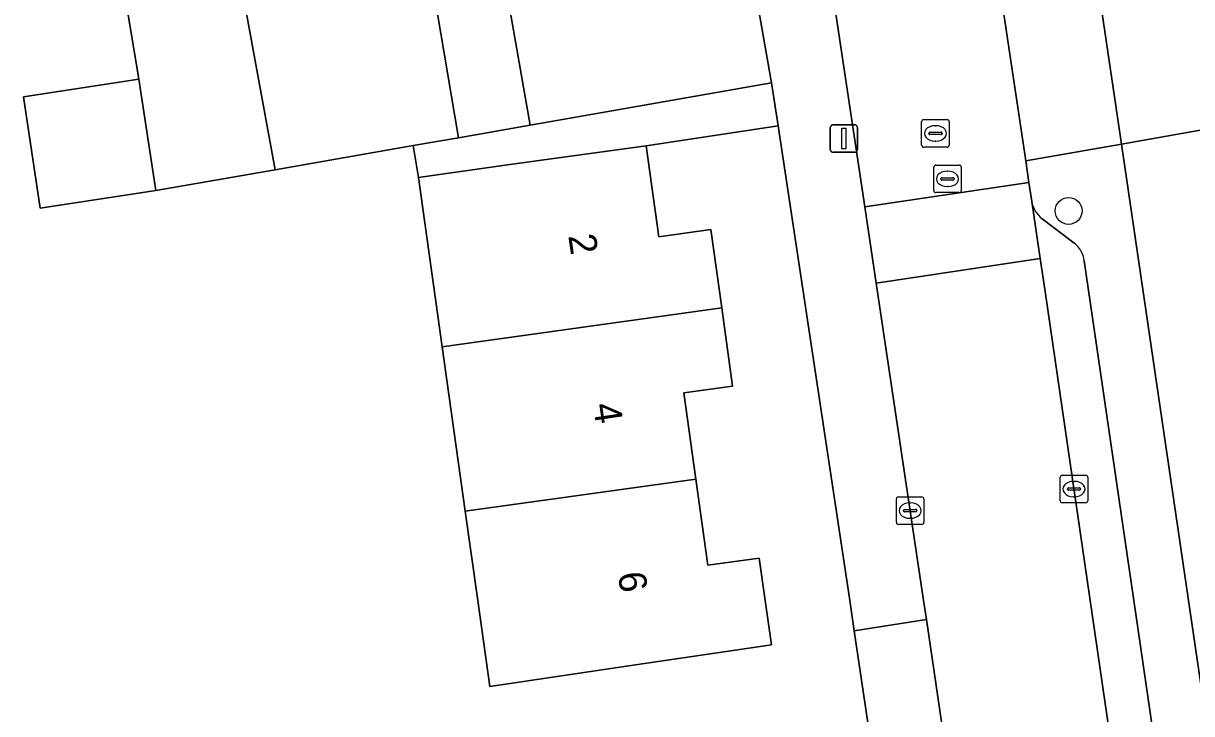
# Model space of a CAD drawing. Extents: x 159053 to 160042, y 380449 to 381423.
# Drawn here: x 159449.7 to 159492.17, y 381245.81 to 381270.89 of the extents above; entities that cross this region are included whole.
import ezdxf

# ---------------------------------------------------------------- set-up
doc = ezdxf.new("R2010")
doc.units = 0
for name, color, linetype in [('IMGEO_Boom', 7, 'Continuous'), ('IMGEO_Erf', 7, 'Continuous'), ('IMGEO_Inrit_open', 7, 'Continuous'), ('IMGEO_Kolk', 7, 'Continuous'), ('IMGEO_Lichtmast', 7, 'Continuous'), ('IMGEO_Pand', 7, 'Continuous'), ('IMGEO_Pand_nummerreeks', 7, 'Continuous'), ('IMGEO_Parkeervlak_open', 7, 'Continuous'), ('IMGEO_Rijbaan_lokaal_open', 7, 'Continuous'), ('IMGEO_Rioolput', 7, 'Continuous'), ('IMGEO_Voetpad_open', 7, 'Continuous')]:
    doc.layers.add(name, color=color, linetype=linetype)

msp = doc.modelspace()

# ---------------------------------------------------------------- linework, layer by layer
at = {"layer": 'IMGEO_Boom'}
msp.add_circle((159487.7, 381264.074), 0.489, dxfattribs=at)
at = {"layer": 'IMGEO_Erf'}
for points in [[(159464.93, 381259.134), (159464.069, 381265.292), (159463.868, 381266.446), (159458.856, 381265.571), (159454.511, 381264.813), (159450.316, 381264.174), (159449.701, 381268.222), (159453.895, 381268.86), (159452.908, 381274.851)], [(159464.746, 381271.31), (159465.519, 381266.734), (159468.12, 381267.188), (159467.326, 381271.758)], [(159480.617, 381244.005), (159479.909, 381248.818), (159479.731, 381250), (159477.138, 381267.167), (159472.343, 381266.443), (159472.803, 381263.137), (159474.692, 381263.4), (159475.088, 381260.552), (159475.485, 381257.704), (159473.711, 381257.458), (159474.146, 381254.33), (159474.581, 381251.2), (159476.448, 381251.46), (159476.655, 381250), (159476.896, 381248.305), (159471.95, 381247.577), (159466.654, 381246.797), (159466.206, 381250), (159465.764, 381253.165), (159464.93, 381259.134)], [(159493.853, 381267.251), (159489.62, 381266.493), (159492.045, 381250), (159496.747, 381218.013)]]:
    msp.add_lwpolyline(points, dxfattribs=at)
at = {"layer": 'IMGEO_Inrit_open'}
msp.add_lwpolyline([(159488.87, 381271.571), (159488.814, 381271.948), (159485.313, 381271.467), (159486.141, 381265.894), (159489.62, 381266.493)], close=True, dxfattribs=at)
at = {"layer": 'IMGEO_Kolk'}
for p, q in [((159487.395, 381253.542), (159487.395, 381254.394)), ((159487.47, 381254.468), (159488.322, 381254.468)), ((159487.883, 381254.248), (159487.908, 381254.248)), ((159488.396, 381254.394), (159488.396, 381253.542)), ((159481.513, 381253.685), (159482.365, 381253.685)), ((159487.654, 381253.962), (159487.654, 381253.974)), ((159488.092, 381253.925), (159487.694, 381253.925)), ((159487.697, 381254.011), (159488.095, 381254.011)), ((159487.906, 381253.688), (159487.881, 381253.688)), ((159488.138, 381253.974), (159488.138, 381253.962)), ((159481.438, 381252.759), (159481.438, 381253.611)), ((159481.926, 381253.465), (159481.951, 381253.465)), ((159482.439, 381253.611), (159482.439, 381252.759)), ((159488.322, 381253.468), (159487.47, 381253.468)), ((159481.697, 381253.179), (159481.697, 381253.191)), ((159482.135, 381253.142), (159481.737, 381253.142)), ((159481.74, 381253.228), (159482.138, 381253.228)), ((159481.949, 381252.905), (159481.924, 381252.905)), ((159482.181, 381253.191), (159482.181, 381253.179)), ((159482.365, 381252.685), (159481.513, 381252.685))]:
    msp.add_line(p, q, dxfattribs=at)
for points in [[(159487.395, 381253.542), (159487.395, 381254.394)], [(159487.47, 381254.468), (159488.322, 381254.468)], [(159488.396, 381254.394), (159488.396, 381253.542)], [(159481.513, 381253.685), (159482.365, 381253.685)], [(159481.438, 381252.759), (159481.438, 381253.611)], [(159482.439, 381253.611), (159482.439, 381252.759)], [(159488.322, 381253.468), (159487.47, 381253.468)], [(159482.365, 381252.685), (159481.513, 381252.685)]]:
    msp.add_lwpolyline(points, dxfattribs=at)
for centre, radius, start, end in [((159487.472, 381254.392), 0.0765, 91.552, 178.448), ((159487.472, 381254.392), 0.0765, 91.552, 178.448), ((159488.32, 381254.392), 0.0765, 1.552, 88.448), ((159488.32, 381254.392), 0.0765, 1.552, 88.448), ((159481.515, 381253.609), 0.0765, 91.552, 178.448), ((159481.515, 381253.609), 0.0765, 91.552, 178.448), ((159482.363, 381253.609), 0.0765, 1.552, 88.448), ((159482.363, 381253.609), 0.0765, 1.552, 88.448), ((159487.694, 381253.971), 0.0403, 85.8775, 175.7526), ((159487.691, 381253.961), 0.0366, 178.938, 274.7102), ((159488.095, 381253.968), 0.043, 264.8664, 352.4533), ((159488.099, 381253.973), 0.0386, 1.7309, 96.639), ((159487.472, 381253.544), 0.0765, 181.552, 268.448), ((159487.472, 381253.544), 0.0765, 181.552, 268.448), ((159488.32, 381253.544), 0.0765, 271.552, 358.448), ((159488.32, 381253.544), 0.0765, 271.552, 358.448), ((159481.737, 381253.188), 0.0403, 85.8775, 175.7526), ((159481.734, 381253.178), 0.0366, 178.938, 274.7102), ((159482.138, 381253.185), 0.043, 264.8664, 352.4533), ((159482.142, 381253.19), 0.0386, 1.7309, 96.639), ((159481.515, 381252.761), 0.0765, 181.552, 268.448), ((159481.515, 381252.761), 0.0765, 181.552, 268.448), ((159482.363, 381252.761), 0.0765, 271.552, 358.448), ((159482.363, 381252.761), 0.0765, 271.552, 358.448)]:
    msp.add_arc(centre, radius, start, end, dxfattribs=at)
for centre, major_axis, ratio, start_param, end_param in [((159487.882, 381253.968), (-0.387, 0.002), 0.722429, 4.712389, 7.853982), ((159487.907, 381253.968), (-0.39, 0.002), 0.717154, 1.570796, 4.712389), ((159481.925, 381253.185), (-0.387, 0.002), 0.722429, 4.712389, 7.853982), ((159481.95, 381253.185), (-0.39, 0.002), 0.717154, 1.570796, 4.712389)]:
    msp.add_ellipse(centre, major_axis=major_axis, ratio=ratio, start_param=start_param, end_param=end_param, dxfattribs=at)
at = {"layer": 'IMGEO_Lichtmast'}
for p, q in [((159479.034, 381266.304), (159479.034, 381267.104)), ((159479.034, 381267.104), (159479.034, 381266.304)), ((159479.134, 381267.204), (159479.924, 381267.204)), ((159479.924, 381267.204), (159479.134, 381267.204)), ((159480.024, 381267.104), (159480.024, 381266.304)), ((159480.024, 381266.304), (159480.024, 381267.104)), ((159479.924, 381266.204), (159479.134, 381266.204)), ((159479.134, 381266.204), (159479.924, 381266.204))]:
    msp.add_line(p, q, dxfattribs=at)
msp.add_lwpolyline([(159479.454, 381267.079), (159479.604, 381267.079), (159479.604, 381266.329), (159479.454, 381266.329), (159479.454, 381267.079)], dxfattribs=at)
for centre, start, end in [((159479.134, 381267.104), 90, 180), ((159479.134, 381267.104), 90, 180), ((159479.924, 381267.104), 0, 90), ((159479.924, 381267.104), 360, 90), ((159479.134, 381266.304), 180, 270), ((159479.134, 381266.304), 180, 270), ((159479.924, 381266.304), 270, 0), ((159479.924, 381266.304), 270, 0)]:
    msp.add_arc(centre, 0.1, start, end, dxfattribs=at)
at = {"layer": 'IMGEO_Pand'}
for points in [[(159458.856, 381265.571), (159457.03, 381275.544), (159452.908, 381274.851), (159453.895, 381268.86), (159454.511, 381264.813)], [(159464.012, 381275.652), (159460.304, 381275.025), (159457.03, 381275.544), (159458.856, 381265.571), (159463.868, 381266.446), (159465.519, 381266.734), (159464.746, 381271.31)], [(159476.317, 381272.048), (159473.321, 381271.528), (159473.107, 381272.762), (159467.326, 381271.758), (159468.12, 381267.188), (159476.903, 381268.722)], [(159454.511, 381264.813), (159453.895, 381268.86), (159449.701, 381268.222), (159450.316, 381264.174)], [(159464.93, 381259.134), (159475.088, 381260.552), (159474.692, 381263.4), (159472.803, 381263.137), (159472.343, 381266.443), (159467.391, 381265.754), (159464.069, 381265.292)], [(159464.93, 381259.134), (159465.764, 381253.165), (159474.146, 381254.33), (159473.711, 381257.458), (159475.485, 381257.704), (159475.088, 381260.552)], [(159465.764, 381253.165), (159466.206, 381250), (159466.654, 381246.797), (159471.95, 381247.577), (159476.896, 381248.305), (159476.655, 381250), (159476.448, 381251.46), (159474.581, 381251.2), (159474.146, 381254.33)]]:
    msp.add_lwpolyline(points, close=True, dxfattribs=at)
at = {"layer": 'IMGEO_Parkeervlak_open'}
for points in [[(159486.361, 381264.417), (159486.669, 381262.342), (159486.847, 381261.146), (159488.473, 381250), (159492.258, 381224.048), (159493.062, 381218.662)], [(159487.888, 381262.912), (159486.742, 381263.785)], [(159494.208, 381221.574), (159490.06, 381250), (159488.271, 381262.261)]]:
    msp.add_lwpolyline(points, dxfattribs=at)
for centre, radius, start, end in [((159487.317, 381264.563), 0.967, 188.6582, 233.509), ((159487.278, 381262.115), 1.004, 8.3707, 52.5681)]:
    msp.add_arc(centre, radius, start, end, dxfattribs=at)
at = {"layer": 'IMGEO_Rijbaan_lokaal_open'}
for points in [[(159485.313, 381271.467), (159484.524, 381276.78), (159484.001, 381280.293), (159483.708, 381282.207), (159481.469, 381296.819), (159481.293, 381297.861), (159481.275, 381298.091), (159475.346, 381297.113), (159475.58, 381295.695), (159475.809, 381294.223), (159476.504, 381289.652), (159478.964, 381273.094), (159479.515, 381269.384), (159480.289, 381264.217), (159486.258, 381265.111), (159486.141, 381265.894)], [(159486.361, 381264.417), (159486.258, 381265.111), (159480.289, 381264.217), (159480.703, 381261.448), (159486.669, 381262.342)], [(159488.473, 381250), (159486.847, 381261.146), (159486.669, 381262.342), (159480.703, 381261.448), (159482.417, 381250), (159482.532, 381249.232), (159483.241, 381244.433), (159487.143, 381218.031), (159487.557, 381215.23), (159487.948, 381212.582), (159493.859, 381213.326), (159493.18, 381217.872), (159493.062, 381218.662), (159492.258, 381224.048)]]:
    msp.add_lwpolyline(points, close=True, dxfattribs=at)
msp.add_lwpolyline([(159488.87, 381271.571), (159489.62, 381266.493), (159493.853, 381267.251), (159498.8, 381267.979), (159500, 381268.146), (159502.734, 381268.528), (159511.925, 381269.766), (159517.86, 381270.631), (159518.629, 381265.35), (159520.146, 381265.571), (159539.599, 381268.207), (159539.222, 381268.657), (159538.088, 381270.011), (159530.524, 381278.017)], dxfattribs=at)
at = {"layer": 'IMGEO_Rioolput'}
for p, q in [((159482.358, 381266.463), (159482.358, 381267.315)), ((159482.433, 381267.389), (159483.285, 381267.389)), ((159483.359, 381267.315), (159483.359, 381266.463)), ((159482.617, 381266.883), (159482.617, 381266.895)), ((159483.055, 381266.846), (159482.657, 381266.846)), ((159482.66, 381266.932), (159483.058, 381266.932)), ((159482.846, 381267.169), (159482.871, 381267.169)), ((159483.101, 381266.895), (159483.101, 381266.883)), ((159482.869, 381266.609), (159482.844, 381266.609)), ((159483.285, 381266.389), (159482.433, 381266.389)), ((159482.797, 381264.811), (159482.797, 381265.663)), ((159482.872, 381265.737), (159483.724, 381265.737)), ((159483.798, 381265.663), (159483.798, 381264.811)), ((159483.056, 381265.231), (159483.056, 381265.243)), ((159483.494, 381265.194), (159483.096, 381265.194)), ((159483.099, 381265.28), (159483.497, 381265.28)), ((159483.285, 381265.517), (159483.31, 381265.517)), ((159483.54, 381265.243), (159483.54, 381265.231)), ((159483.724, 381264.737), (159482.872, 381264.737)), ((159483.308, 381264.957), (159483.283, 381264.957))]:
    msp.add_line(p, q, dxfattribs=at)
for points in [[(159482.358, 381266.463), (159482.358, 381267.315)], [(159482.433, 381267.389), (159483.285, 381267.389)], [(159483.359, 381267.315), (159483.359, 381266.463)], [(159483.285, 381266.389), (159482.433, 381266.389)], [(159482.797, 381264.811), (159482.797, 381265.663)], [(159482.872, 381265.737), (159483.724, 381265.737)], [(159483.798, 381265.663), (159483.798, 381264.811)], [(159483.724, 381264.737), (159482.872, 381264.737)]]:
    msp.add_lwpolyline(points, dxfattribs=at)
for centre, radius, start, end in [((159482.435, 381267.313), 0.0765, 91.552, 178.448), ((159482.435, 381267.313), 0.0765, 91.552, 178.448), ((159483.283, 381267.313), 0.0765, 1.552, 88.448), ((159483.283, 381267.313), 0.0765, 1.552, 88.448), ((159482.657, 381266.892), 0.0403, 85.8775, 175.7526), ((159482.654, 381266.882), 0.0366, 178.938, 274.7102), ((159483.058, 381266.889), 0.043, 264.8664, 352.4533), ((159483.062, 381266.894), 0.0386, 1.7309, 96.639), ((159482.435, 381266.465), 0.0765, 181.552, 268.448), ((159482.435, 381266.465), 0.0765, 181.552, 268.448), ((159483.283, 381266.465), 0.0765, 271.552, 358.448), ((159483.283, 381266.465), 0.0765, 271.552, 358.448), ((159482.874, 381265.661), 0.0765, 91.552, 178.448), ((159482.874, 381265.661), 0.0765, 91.552, 178.448), ((159483.722, 381265.661), 0.0765, 1.552, 88.448), ((159483.722, 381265.661), 0.0765, 1.552, 88.448), ((159483.096, 381265.24), 0.0403, 85.8775, 175.7526), ((159483.093, 381265.23), 0.0366, 178.938, 274.7102), ((159483.497, 381265.237), 0.043, 264.8664, 352.4533), ((159483.501, 381265.242), 0.0386, 1.7309, 96.639), ((159482.874, 381264.813), 0.0765, 181.552, 268.448), ((159482.874, 381264.813), 0.0765, 181.552, 268.448), ((159483.722, 381264.813), 0.0765, 271.552, 358.448), ((159483.722, 381264.813), 0.0765, 271.552, 358.448)]:
    msp.add_arc(centre, radius, start, end, dxfattribs=at)
for centre, major_axis, ratio, start_param, end_param in [((159482.845, 381266.889), (-0.387, 0.002), 0.722429, 4.712389, 7.853982), ((159482.87, 381266.889), (-0.39, 0.002), 0.717154, 1.570796, 4.712389), ((159483.284, 381265.237), (-0.387, 0.002), 0.722429, 4.712389, 7.853982), ((159483.309, 381265.237), (-0.39, 0.002), 0.717154, 1.570796, 4.712389)]:
    msp.add_ellipse(centre, major_axis=major_axis, ratio=ratio, start_param=start_param, end_param=end_param, dxfattribs=at)
at = {"layer": 'IMGEO_Voetpad_open'}
for points in [[(159478.964, 381273.094), (159476.504, 381289.652), (159475.809, 381294.223), (159475.58, 381295.695), (159475.346, 381297.113), (159474.689, 381296.791), (159476.092, 381288.641), (159476.495, 381286.027), (159474.65, 381284.007), (159476.1, 381273.282), (159476.317, 381272.048), (159476.903, 381268.722), (159477.138, 381267.167), (159479.731, 381250), (159479.909, 381248.818), (159482.532, 381249.232), (159482.417, 381250), (159480.703, 381261.448), (159480.289, 381264.217), (159479.515, 381269.384)], [(159477.138, 381267.167), (159476.903, 381268.722), (159468.12, 381267.188), (159465.519, 381266.734), (159463.868, 381266.446), (159464.069, 381265.292), (159467.391, 381265.754), (159472.343, 381266.443)], [(159482.532, 381249.232), (159479.909, 381248.818), (159480.617, 381244.005), (159483.241, 381244.433)]]:
    msp.add_lwpolyline(points, close=True, dxfattribs=at)
for points in [[(159489.62, 381266.493), (159486.141, 381265.894), (159486.258, 381265.111), (159486.361, 381264.417)], [(159493.062, 381218.662), (159493.18, 381217.872), (159496.747, 381218.013), (159492.045, 381250), (159489.62, 381266.493)], [(159486.742, 381263.785), (159487.888, 381262.912)], [(159488.271, 381262.261), (159490.06, 381250), (159494.208, 381221.574)]]:
    msp.add_lwpolyline(points, dxfattribs=at)
for centre, radius, start, end in [((159487.317, 381264.563), 0.967, 188.6582, 233.509), ((159487.278, 381262.115), 1.004, 8.3707, 52.5681)]:
    msp.add_arc(centre, radius, start, end, dxfattribs=at)

# ---------------------------------------------------------------- texts
at = {"layer": 'IMGEO_Pand_nummerreeks'}
for s, p in [('2', (159469.508, 381263.172)), ('4', (159470.41, 381257.033)), ('6', (159471.311, 381250.897))]:
    msp.add_text(s, height=1, rotation=278.3561, dxfattribs=at).set_placement(p)

doc.saveas('drawing.dxf')
